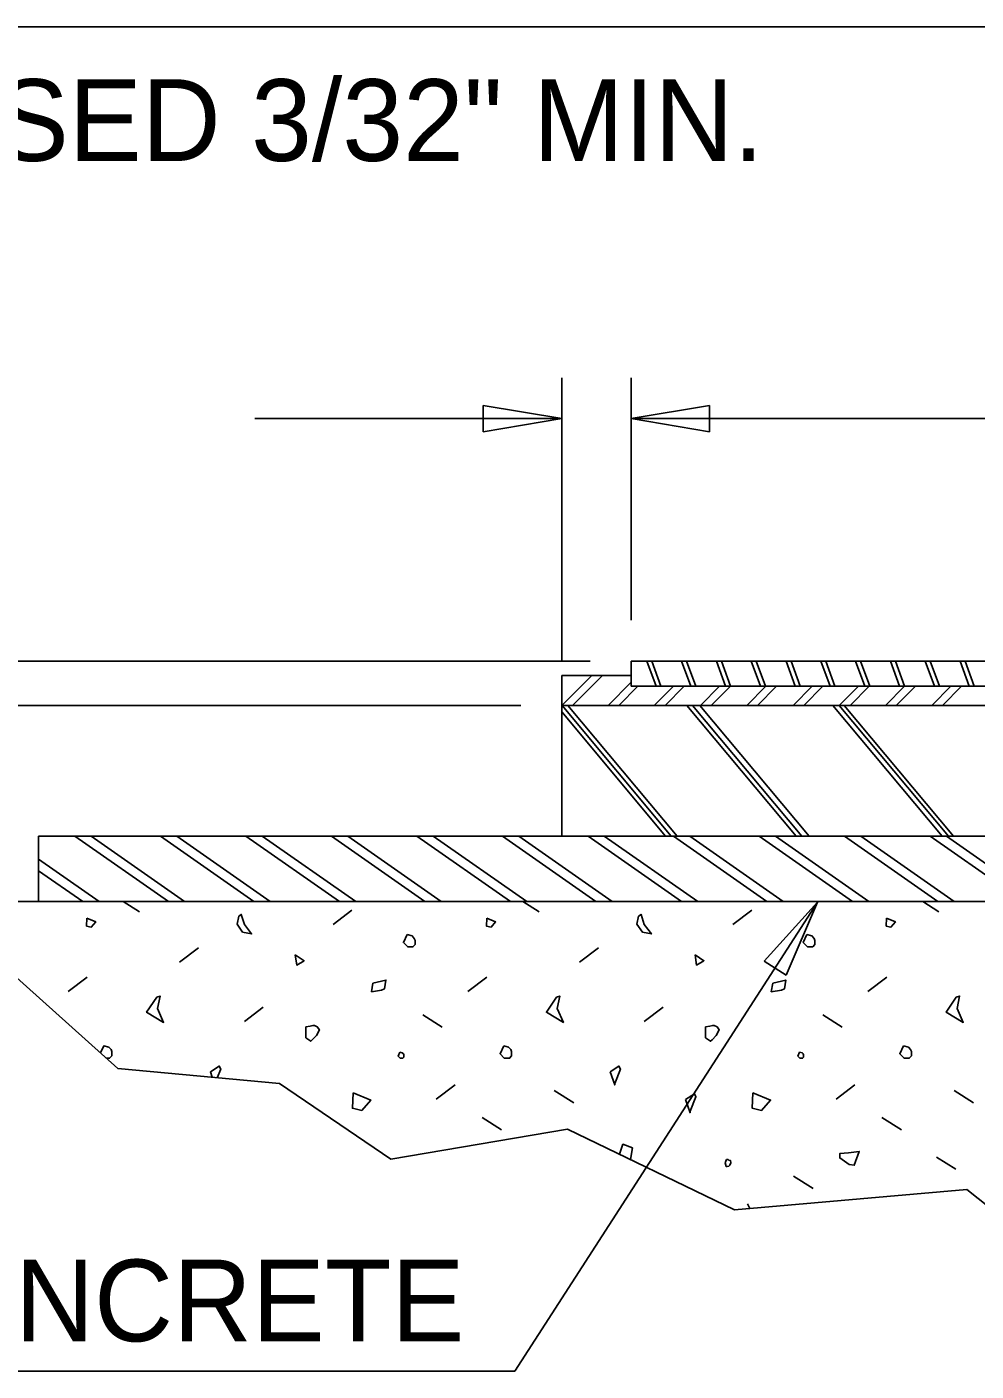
# Model space of a CAD drawing. Extents: x 0 to 22.7, y 0 to 15.7.
# Drawn here: x 9.92 to 11.13, y 2.563 to 4.276 of the extents above; entities that cross this region are included whole.
import ezdxf

# ---------------------------------------------------------------- set-up
doc = ezdxf.new("R2010")
doc.units = 0
for name, color, linetype in [('BRDG_ANNO_General-Notes', 7, 'Continuous'), ('BRDG_BASE_Obj-Line', 7, 'Continuous'), ('BRDG_BASE_Pattern', 7, 'Continuous'), ('BRDG_BASE_Phtline', 7, 'Continuous')]:
    doc.layers.add(name, color=color, linetype=linetype)

msp = doc.modelspace()

# ---------------------------------------------------------------- linework, layer by layer
at = {"layer": 'BRDG_ANNO_General-Notes'}
for p, q in [((11.5011, 4.2765), (9.3368, 4.2765)), ((10.6017, 3.469), (10.6017, 3.8293)), ((10.6901, 3.5203), (10.6901, 3.8293)), ((10.5017, 3.7605), (10.5017, 3.7939)), ((10.5017, 3.7939), (10.6017, 3.7772)), ((10.6901, 3.7772), (10.7901, 3.7939)), ((10.7901, 3.7939), (10.7901, 3.7605)), ((10.6017, 3.7772), (10.2108, 3.7772)), ((10.6017, 3.7772), (10.5017, 3.7605)), ((10.6901, 3.7772), (11.748, 3.7772)), ((10.7901, 3.7605), (10.6901, 3.7772)), ((10.638, 3.4682), (9.6571, 3.4682)), ((10.5496, 3.4117), (9.4351, 3.4117)), ((10.9276, 3.1607), (10.542, 2.5632)), ((10.8594, 3.0857), (10.9276, 3.1607)), ((10.9276, 3.1607), (10.8874, 3.0677)), ((10.8874, 3.0677), (10.8594, 3.0857)), ((10.542, 2.5632), (9.0706, 2.5632))]:
    msp.add_line(p, q, dxfattribs=at)
at = {"layer": 'BRDG_BASE_Obj-Line'}
for p, q in [((10.6901, 3.4682), (11.748, 3.4682)), ((10.6901, 3.436), (10.6901, 3.4682)), ((10.6017, 3.4498), (10.6901, 3.4498)), ((10.6017, 3.4117), (10.6017, 3.4497)), ((10.6901, 3.436), (11.748, 3.436)), ((10.6017, 3.2449), (10.6017, 3.4117)), ((10.6017, 3.4117), (11.8517, 3.4117)), ((9.9351, 3.2449), (10.6017, 3.2449)), ((9.9351, 3.1616), (9.9351, 3.2449)), ((12.5184, 3.2449), (10.6017, 3.2449)), ((9.7986, 3.1616), (9.9351, 3.1616)), ((9.9351, 3.1616), (12.8529, 3.1616))]:
    msp.add_line(p, q, dxfattribs=at)
msp.add_lwpolyline([(9.7986, 3.1616), (10.0361, 2.9491), (10.2421, 2.9298), (10.3838, 2.8332), (10.6092, 2.8718), (10.8216, 2.7687), (11.1178, 2.7945), (11.2723, 2.6721), (11.5492, 2.7236), (11.7359, 2.6656), (11.9741, 2.7107), (12.1479, 2.6721), (12.3475, 2.7558), (12.4892, 2.6785), (12.7016, 2.6979), (12.8175, 2.6077), (12.9849, 2.6785), (13.0952, 2.6656)], dxfattribs=at)
at = {"layer": 'BRDG_BASE_Pattern'}
for p, q in [((10.7218, 3.436), (10.7101, 3.4682)), ((10.7281, 3.436), (10.7165, 3.4682)), ((10.7661, 3.436), (10.7544, 3.4682)), ((10.7724, 3.436), (10.7608, 3.4682)), ((10.8105, 3.436), (10.7988, 3.4682)), ((10.8168, 3.436), (10.8051, 3.4682)), ((10.8548, 3.436), (10.8431, 3.4682)), ((10.8611, 3.436), (10.8495, 3.4682)), ((10.8992, 3.436), (10.8874, 3.4682)), ((10.9055, 3.436), (10.8938, 3.4682)), ((10.9435, 3.436), (10.9318, 3.4682)), ((10.9498, 3.436), (10.9381, 3.4682)), ((10.9879, 3.436), (10.9761, 3.4682)), ((10.9942, 3.436), (10.9825, 3.4682)), ((11.0322, 3.436), (11.0205, 3.4682)), ((11.0385, 3.436), (11.0268, 3.4682)), ((11.0765, 3.436), (11.0648, 3.4682)), ((11.0829, 3.436), (11.0711, 3.4682)), ((11.1209, 3.436), (11.1092, 3.4682)), ((11.1272, 3.436), (11.1155, 3.4682)), ((10.6017, 3.4117), (10.6398, 3.4498)), ((10.6154, 3.4117), (10.6535, 3.4498)), ((10.6606, 3.4117), (10.6901, 3.4411)), ((10.6743, 3.4117), (10.6986, 3.436)), ((10.7196, 3.4117), (10.7439, 3.436)), ((10.7333, 3.4117), (10.7576, 3.436)), ((10.7785, 3.4117), (10.8028, 3.436)), ((10.7922, 3.4117), (10.8165, 3.436)), ((10.8374, 3.4117), (10.8617, 3.436)), ((10.8511, 3.4117), (10.8754, 3.436)), ((10.8964, 3.4117), (10.9207, 3.436)), ((10.9101, 3.4117), (10.9344, 3.436)), ((10.9553, 3.4117), (10.9796, 3.436)), ((10.969, 3.4117), (10.9933, 3.436)), ((11.0142, 3.4117), (11.0385, 3.436)), ((11.0279, 3.4117), (11.0522, 3.436)), ((11.0731, 3.4117), (11.0974, 3.436)), ((11.0868, 3.4117), (11.1111, 3.436)), ((10.6017, 3.4117), (10.6017, 3.4117)), ((10.1004, 3.1616), (9.9814, 3.2449)), ((10.1211, 3.1616), (10.0021, 3.2449)), ((10.2093, 3.1616), (10.0903, 3.2449)), ((10.2301, 3.1616), (10.1111, 3.2449)), ((10.3183, 3.1616), (10.1993, 3.2449)), ((10.3391, 3.1616), (10.2201, 3.2449)), ((10.4272, 3.1616), (10.3082, 3.2449)), ((10.448, 3.1616), (10.329, 3.2449)), ((10.5362, 3.1616), (10.4172, 3.2449)), ((10.557, 3.1616), (10.438, 3.2449)), ((10.6452, 3.1616), (10.5262, 3.2449)), ((10.666, 3.1616), (10.547, 3.2449)), ((10.7542, 3.1616), (10.6352, 3.2449)), ((10.7749, 3.1616), (10.6559, 3.2449)), ((10.8631, 3.1616), (10.7441, 3.2449)), ((10.8839, 3.1616), (10.7649, 3.2449)), ((10.9721, 3.1616), (10.8531, 3.2449)), ((10.9929, 3.1616), (10.8739, 3.2449)), ((11.081, 3.1616), (10.962, 3.2449)), ((11.1018, 3.1616), (10.9828, 3.2449)), ((11.19, 3.1616), (11.071, 3.2449)), ((11.2108, 3.1616), (11.0918, 3.2449)), ((10.0122, 3.1616), (9.9351, 3.2156)), ((9.9914, 3.1616), (9.9351, 3.201)), ((10.0428, 3.1616), (10.0635, 3.1485)), ((10.5522, 3.1616), (10.5729, 3.1485)), ((11.0616, 3.1616), (11.0823, 3.1485)), ((10.3344, 3.1506), (10.3104, 3.1323)), ((10.8439, 3.1506), (10.8198, 3.1323)), ((10.1389, 3.1029), (10.1148, 3.0845)), ((10.6483, 3.1029), (10.6242, 3.0845)), ((9.9969, 3.0655), (9.9728, 3.0472)), ((10.5063, 3.0655), (10.4822, 3.0472)), ((11.0157, 3.0655), (10.9916, 3.0472)), ((10.2214, 3.0272), (10.1973, 3.009)), ((10.4248, 3.0174), (10.4495, 3.0018)), ((10.7308, 3.0272), (10.7067, 3.009)), ((10.9342, 3.0174), (10.959, 3.0018)), ((10.4658, 2.9281), (10.4417, 2.9098)), ((10.5922, 2.9207), (10.6169, 2.9052)), ((10.9752, 2.9281), (10.9511, 2.9098)), ((11.1016, 2.9207), (11.1263, 2.9052)), ((10.5002, 2.8865), (10.525, 2.8709)), ((11.0096, 2.8865), (11.0344, 2.8709)), ((11.0791, 2.8361), (11.1039, 2.8205)), ((10.897, 2.8116), (10.9218, 2.796)), ((10.8383, 2.7763), (10.8413, 2.7704))]:
    msp.add_line(p, q, dxfattribs=at)
for points in [[(9.9967, 3.1404), (9.9962, 3.1305), (10.0022, 3.1291), (10.008, 3.1358)], [(10.1901, 3.1432), (10.1881, 3.1328), (10.1949, 3.1227), (10.2065, 3.1204), (10.1973, 3.1326), (10.1933, 3.1452)], [(10.5061, 3.1404), (10.5056, 3.1305), (10.5116, 3.1291), (10.5174, 3.1358)], [(10.6995, 3.1432), (10.6975, 3.1328), (10.7044, 3.1227), (10.7159, 3.1204), (10.7067, 3.1326), (10.7028, 3.1452)], [(11.0155, 3.1404), (11.0151, 3.1305), (11.021, 3.1291), (11.0268, 3.1358)], [(10.4046, 3.1196), (10.4, 3.1095), (10.4054, 3.1039), (10.412, 3.1039), (10.4147, 3.1068), (10.4147, 3.1122), (10.4138, 3.1148), (10.4109, 3.1178)], [(10.914, 3.1196), (10.9094, 3.1095), (10.9148, 3.1039), (10.9214, 3.1039), (10.9241, 3.1068), (10.9241, 3.1122), (10.9232, 3.1148), (10.9204, 3.1178)], [(10.2622, 3.0936), (10.2641, 3.0807), (10.2733, 3.0863)], [(10.7716, 3.0936), (10.7735, 3.0807), (10.7827, 3.0863)], [(10.3611, 3.0578), (10.3593, 3.0468), (10.3722, 3.0486), (10.3758, 3.0505), (10.3777, 3.0615)], [(10.8705, 3.0578), (10.8686, 3.0468), (10.8816, 3.0486), (10.8853, 3.0505), (10.8871, 3.0615)], [(10.0856, 3.04), (10.0727, 3.0207), (10.0944, 3.0077), (10.0865, 3.0253), (10.0898, 3.0413)], [(10.5949, 3.04), (10.5821, 3.0207), (10.6037, 3.0077), (10.5958, 3.0253), (10.5992, 3.0413)], [(11.1044, 3.04), (11.0915, 3.0207), (11.1132, 3.0077), (11.1053, 3.0253), (11.1086, 3.0413)], [(10.2755, 3.0021), (10.2755, 2.9882), (10.2818, 2.9837), (10.2837, 2.9855), (10.2892, 2.991), (10.2929, 2.9984), (10.2902, 3.0021), (10.2865, 3.0039), (10.2847, 3.0039), (10.2811, 3.0029)], [(10.7849, 3.0021), (10.7849, 2.9882), (10.7912, 2.9837), (10.7932, 2.9855), (10.7986, 2.991), (10.8023, 2.9984), (10.7996, 3.0021), (10.7959, 3.0039), (10.7941, 3.0039), (10.7905, 3.0029)], [(10.3954, 2.9699), (10.3931, 2.9648), (10.3958, 2.962), (10.3991, 2.962), (10.4005, 2.9635), (10.4005, 2.9662), (10.4, 2.9676), (10.3985, 2.969)], [(10.5277, 2.9778), (10.523, 2.9677), (10.5284, 2.962), (10.5351, 2.962), (10.5378, 2.9649), (10.5378, 2.9704), (10.5368, 2.973), (10.534, 2.976)], [(10.9048, 2.9699), (10.9025, 2.9648), (10.9052, 2.962), (10.9085, 2.962), (10.9098, 2.9635), (10.9098, 2.9662), (10.9094, 2.9676), (10.908, 2.969)], [(11.037, 2.9778), (11.0324, 2.9677), (11.0378, 2.962), (11.0444, 2.962), (11.0471, 2.9649), (11.0471, 2.9704), (11.0462, 2.973), (11.0434, 2.976)], [(10.6634, 2.9445), (10.6691, 2.9279), (10.6691, 2.9297), (10.6765, 2.9482), (10.6746, 2.9519)], [(10.3358, 2.918), (10.3349, 2.8982), (10.3469, 2.8954), (10.3584, 2.9087)], [(10.7595, 2.9092), (10.7652, 2.8926), (10.7652, 2.8944), (10.7726, 2.9129), (10.7707, 2.9165)], [(10.8452, 2.918), (10.8443, 2.8982), (10.8562, 2.8954), (10.8678, 2.9087)], [(10.8098, 2.8287), (10.8112, 2.8241), (10.8126, 2.8241), (10.8145, 2.8246), (10.8158, 2.8259), (10.8172, 2.8287), (10.8168, 2.8315), (10.8145, 2.8319), (10.8135, 2.8329), (10.8117, 2.8329)], [(10.9669, 2.8414), (10.9559, 2.8404), (10.9559, 2.8349), (10.9679, 2.8267), (10.9744, 2.8257), (10.9808, 2.8432)]]:
    msp.add_lwpolyline(points, close=True, dxfattribs=at)
for points in [[(10.0217, 2.962), (10.0256, 2.962), (10.0283, 2.9649), (10.0283, 2.9704), (10.0274, 2.973), (10.0246, 2.976), (10.0182, 2.9778), (10.0141, 2.9688)], [(10.1628, 2.9372), (10.1671, 2.9482), (10.1652, 2.9519), (10.154, 2.9445), (10.1563, 2.9379)], [(10.6891, 2.833), (10.6916, 2.8478), (10.6796, 2.8523), (10.6753, 2.8397)]]:
    msp.add_lwpolyline(points, dxfattribs=at)
at = {"layer": 'BRDG_BASE_Phtline'}
for p, q in [((10.602, 3.4117), (10.7412, 3.2449)), ((10.6095, 3.4117), (10.7488, 3.2449)), ((10.7609, 3.4117), (10.9002, 3.2449)), ((10.7683, 3.4117), (10.9076, 3.2449)), ((10.7774, 3.4117), (10.9167, 3.2449)), ((10.9469, 3.4117), (11.0862, 3.2449)), ((10.9551, 3.4117), (11.0943, 3.2449)), ((10.9616, 3.4117), (11.1008, 3.2449)), ((10.6017, 3.4033), (10.7339, 3.2449))]:
    msp.add_line(p, q, dxfattribs=at)

# ---------------------------------------------------------------- texts
at = {"layer": 'BRDG_ANNO_General-Notes'}
for s, height, p in [('RECESSED 3/32" MIN.', 0.104167, (9.4008, 4.1056)), ('TOP OF CONCRETE', 0.104115, (9.1395, 2.6012))]:
    msp.add_text(s, height=height, dxfattribs=at).set_placement(p)

doc.saveas('drawing.dxf')
